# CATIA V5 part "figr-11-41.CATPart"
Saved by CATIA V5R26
Part number: Part1
Bounding box of the stored display mesh (mm): x -59 to 59, y -60 to 60, z 0 to 39.8
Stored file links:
  D:\_Deepak\CATIA\CATIA V5-6R2016_Deepak\Resources\Part files\Partfiles\c11_catia_v5_6r2016_prt\figr-11-41.CATPart
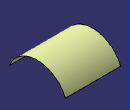
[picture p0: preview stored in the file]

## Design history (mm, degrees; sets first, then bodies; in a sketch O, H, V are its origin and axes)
Set1
  Extrude1: Element1 Sketch1, Lim1 59, Lim2 59, Direction yz-plane
Body1 (main body)
  Sketch1 on yz-plane, origin (0, 0, 0), H (0, 1, 0), V (0, 0, 1)
    arc A1 centre (0, -25) radius 65 from (-60, 0) to (60, 0) cw
    point P2 (-60, 0)
    point P3 (60, 0)
    coincidence: P2 H, P3 H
